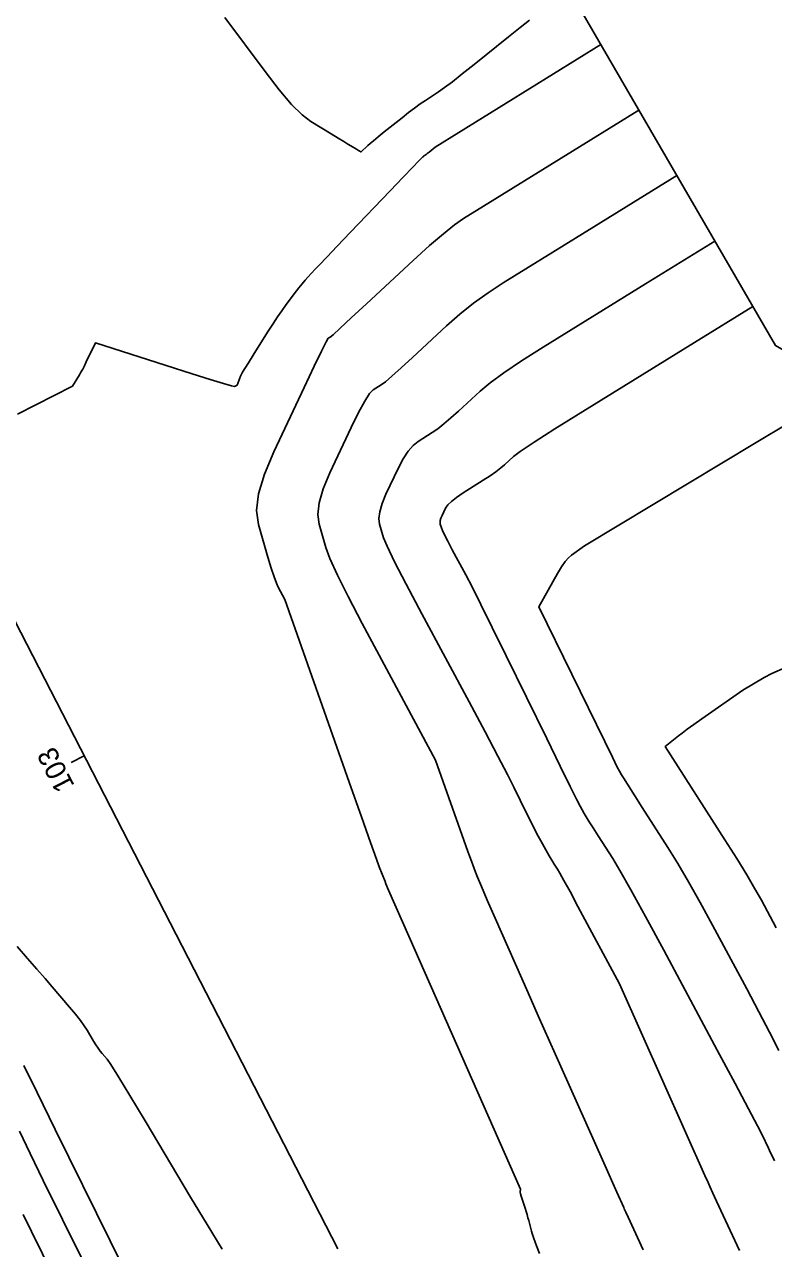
# Model space of a CAD drawing. Extents: x 1715724 to 1716561, y 394063 to 395906.
# Drawn here: x 1716227.9 to 1716279.5, y 394685.4 to 394769.7 of the extents above; entities that cross this region are included whole.
import ezdxf

# ---------------------------------------------------------------- set-up
doc = ezdxf.new("R2010")
doc.units = 0
for name, color, linetype in [('DT_X_Contour_Major', 7, 'Continuous'), ('DT_X_Contour_Minor', 7, 'Continuous'), ('DT_X_TIN_Hull', 7, 'Continuous'), ('GE_P_CL_10', 7, 'Continuous')]:
    doc.layers.add(name, color=color, linetype=linetype)

msp = doc.modelspace()

# ---------------------------------------------------------------- linework, layer by layer
at = {"layer": 'DT_X_Contour_Major'}
for points in [[(1716272.823, 394759.332), (1716265.845, 394755.011), (1716260.865, 394751.933), (1716259.819, 394751.253), (1716258.821, 394750.534), (1716257.87, 394749.777), (1716256.966, 394748.981), (1716254.621, 394746.807), (1716253.825, 394746.078), (1716253.199, 394745.52), (1716252.741, 394745.133), (1716252.452, 394744.917), (1716251.906, 394744.572), (1716251.658, 394744.312), (1716251.324, 394743.792), (1716250.902, 394743.011), (1716250.394, 394741.971), (1716248.923, 394738.849), (1716248.462, 394737.75), (1716248.183, 394736.794), (1716248.086, 394735.982), (1716248.17, 394735.314), (1716248.636, 394733.722), (1716248.925, 394732.948), (1716249.44, 394731.817), (1716250.183, 394730.331), (1716251.152, 394728.489), (1716256.206, 394719.064), (1716258.286, 394713.181), (1716258.43, 394712.779), (1716258.498, 394712.594), (1716258.61, 394712.303), (1716258.77, 394711.863), (1716258.95, 394711.359), (1716259.085, 394711.02), (1716259.357, 394710.38), (1716259.765, 394709.441), (1716260.309, 394708.201), (1716262.583, 394703.046), (1716263.279, 394701.476), (1716264.837, 394697.977), (1716267.799, 394691.34), (1716268.694, 394689.335), (1716269.164, 394688.27), (1716269.205, 394688.179), (1716269.305, 394687.953), (1716269.465, 394687.609), (1716269.869, 394686.746), (1716270.516, 394685.364)], [(1716235.034, 394683.408), (1716233.77, 394685.974), (1716229.993, 394693.646), (1716228.745, 394696.184), (1716227.834, 394698.044)]]:
    msp.add_lwpolyline(points, dxfattribs=at)
at = {"layer": 'DT_X_Contour_Minor'}
for points in [[(1716241.671, 394770.221), (1716244.453, 394766.49), (1716245.432, 394765.226), (1716246.282, 394764.231), (1716247.004, 394763.507), (1716247.598, 394763.052), (1716249.009, 394762.198), (1716249.49, 394761.907), (1716249.876, 394761.673), (1716250.166, 394761.496), (1716250.361, 394761.377), (1716250.753, 394761.136), (1716250.882, 394761.057), (1716250.974, 394761), (1716251.031, 394760.965), (1716251.051, 394760.952), (1716251.06, 394760.945), (1716251.54, 394761.396), (1716251.688, 394761.527), (1716251.925, 394761.726), (1716252.252, 394761.993), (1716252.668, 394762.328), (1716253.897, 394763.313), (1716254.343, 394763.664), (1716254.758, 394763.979), (1716255.144, 394764.258), (1716255.499, 394764.5), (1716256.407, 394765.098), (1716256.816, 394765.383), (1716257.361, 394765.791), (1716258.044, 394766.322), (1716258.863, 394766.976), (1716261.231, 394768.883), (1716262.038, 394769.528), (1716262.682, 394770.033)], [(1716227.391, 394742.901), (1716231.178, 394744.824), (1716231.663, 394745.6), (1716231.771, 394745.781), (1716231.886, 394745.991), (1716232.008, 394746.229), (1716232.138, 394746.496), (1716232.763, 394747.809), (1716239.425, 394745.677), (1716240.679, 394745.28), (1716241.586, 394745.002), (1716242.145, 394744.844), (1716242.358, 394744.805), (1716242.539, 394744.901), (1716242.661, 394745.253), (1716242.687, 394745.325), (1716242.713, 394745.393), (1716242.739, 394745.455), (1716242.765, 394745.512), (1716242.834, 394745.657), (1716242.903, 394745.779), (1716243.059, 394746.036), (1716243.302, 394746.427), (1716243.632, 394746.954), (1716244.626, 394748.538), (1716244.984, 394749.099), (1716245.311, 394749.594), (1716245.607, 394750.024), (1716245.872, 394750.389), (1716246.538, 394751.273), (1716246.779, 394751.588), (1716247.005, 394751.871), (1716247.216, 394752.12), (1716247.41, 394752.337), (1716247.907, 394752.872), (1716248.199, 394753.182), (1716248.701, 394753.71), (1716249.413, 394754.456), (1716250.335, 394755.42), (1716253.075, 394758.282), (1716253.977, 394759.225), (1716254.631, 394759.906), (1716255.036, 394760.327), (1716255.192, 394760.487), (1716255.276, 394760.566), (1716255.306, 394760.594), (1716255.334, 394760.619), (1716255.359, 394760.641), (1716255.381, 394760.659), (1716255.437, 394760.704), (1716255.458, 394760.72), (1716255.476, 394760.734), (1716255.494, 394760.747), (1716255.51, 394760.758), (1716255.552, 394760.785), (1716255.576, 394760.803), (1716255.62, 394760.837), (1716255.682, 394760.886), (1716255.762, 394760.95), (1716256.18, 394761.287), (1716267.588, 394768.353)], [(1716270.205, 394763.842), (1716259.514, 394757.222), (1716258.122, 394756.362), (1716257.515, 394755.94), (1716256.737, 394755.32), (1716255.788, 394754.501), (1716254.667, 394753.483), (1716251.452, 394750.503), (1716250.391, 394749.521), (1716249.618, 394748.811), (1716249.135, 394748.372), (1716248.94, 394748.204), (1716248.807, 394748.12), (1716248.665, 394747.884), (1716248.341, 394747.243), (1716247.834, 394746.194), (1716247.144, 394744.739), (1716245.06, 394740.315), (1716244.407, 394738.758), (1716244.011, 394737.405), (1716243.873, 394736.254), (1716243.993, 394735.307), (1716244.654, 394733.053), (1716244.883, 394732.29), (1716245.075, 394731.693), (1716245.23, 394731.261), (1716245.347, 394730.995), (1716245.806, 394730.138), (1716250.253, 394717.555), (1716251.097, 394715.169), (1716251.724, 394713.403), (1716252.133, 394712.257), (1716252.326, 394711.732), (1716252.722, 394710.714), (1716252.781, 394710.551), (1716252.966, 394710.125), (1716254.365, 394706.944), (1716262.044, 394689.522), (1716262.019, 394689.376), (1716262.024, 394689.319), (1716262.049, 394689.213), (1716262.095, 394689.055), (1716262.161, 394688.848), (1716262.365, 394688.227), (1716262.439, 394687.999), (1716262.507, 394687.779), (1716262.569, 394687.568), (1716262.625, 394687.366), (1716262.819, 394686.65), (1716262.867, 394686.481), (1716262.913, 394686.331), (1716262.955, 394686.201), (1716263.063, 394685.879), (1716263.16, 394685.622), (1716263.368, 394685.092)], [(1716275.44, 394754.821), (1716270.67, 394751.868), (1716263.608, 394747.505), (1716262.123, 394746.566), (1716260.904, 394745.749), (1716259.952, 394745.054), (1716259.265, 394744.48), (1716257.789, 394743.112), (1716257.26, 394742.634), (1716256.779, 394742.228), (1716256.347, 394741.894), (1716255.964, 394741.631), (1716255.006, 394741.024), (1716254.651, 394740.739), (1716254.306, 394740.341), (1716253.971, 394739.829), (1716253.644, 394739.203), (1716252.786, 394737.382), (1716252.517, 394736.741), (1716252.355, 394736.183), (1716252.298, 394735.71), (1716252.347, 394735.32), (1716252.619, 394734.392), (1716252.861, 394733.803), (1716253.381, 394732.734), (1716254.181, 394731.183), (1716255.259, 394729.152), (1716258.507, 394723.094), (1716259.614, 394721.022), (1716260.499, 394719.35), (1716261.161, 394718.079), (1716261.6, 394717.207), (1716262.477, 394715.415), (1716262.784, 394714.792), (1716263.05, 394714.267), (1716263.274, 394713.838), (1716263.455, 394713.508), (1716264.036, 394712.492), (1716264.169, 394712.265), (1716264.284, 394712.075), (1716264.38, 394711.921), (1716264.611, 394711.56), (1716264.764, 394711.298), (1716265.048, 394710.785), (1716265.464, 394710.019), (1716266.012, 394709.001), (1716268.874, 394703.664), (1716274.853, 394690.268), (1716274.906, 394690.147), (1716274.975, 394689.993), (1716275.03, 394689.868), (1716275.1, 394689.712), (1716275.305, 394689.252), (1716275.417, 394689.005), (1716275.856, 394688.061), (1716276.183, 394687.363), (1716277.149, 394685.304)], [(1716278.058, 394750.311), (1716274.052, 394747.834), (1716266.351, 394743.076), (1716264.427, 394741.879), (1716262.988, 394740.963), (1716262.034, 394740.33), (1716261.564, 394739.978), (1716260.958, 394739.416), (1716260.694, 394739.191), (1716260.36, 394738.937), (1716259.953, 394738.655), (1716259.475, 394738.344), (1716258.106, 394737.476), (1716257.645, 394737.166), (1716257.289, 394736.89), (1716257.039, 394736.646), (1716256.894, 394736.435), (1716256.649, 394735.915), (1716256.573, 394735.732), (1716256.526, 394735.573), (1716256.51, 394735.437), (1716256.524, 394735.326), (1716256.602, 394735.061), (1716256.671, 394734.893), (1716256.819, 394734.588), (1716257.048, 394734.145), (1716257.356, 394733.565), (1716258.283, 394731.835), (1716258.718, 394731), (1716259.328, 394729.793), (1716260.112, 394728.213), (1716261.07, 394726.26), (1716263.859, 394720.557), (1716264.788, 394718.662), (1716265.482, 394717.255), (1716265.94, 394716.336), (1716266.164, 394715.906), (1716266.448, 394715.409), (1716266.588, 394715.173), (1716266.795, 394714.837), (1716267.068, 394714.402), (1716267.409, 394713.867), (1716268.406, 394712.31), (1716268.906, 394711.476), (1716269.658, 394710.144), (1716270.663, 394708.312), (1716271.921, 394705.982), (1716275.61, 394699.103), (1716276.841, 394696.804), (1716277.767, 394695.064), (1716278.387, 394693.883), (1716278.702, 394693.262), (1716279.135, 394692.353), (1716279.29, 394692.029), (1716279.433, 394691.741), (1716279.562, 394691.489)], [(1716280.516, 394742.282), (1716278.284, 394740.942), (1716266.468, 394733.83), (1716265.556, 394733.194), (1716265.35, 394733.013), (1716265.124, 394732.742), (1716264.878, 394732.383), (1716264.611, 394731.934), (1716263.32, 394729.629), (1716267.856, 394720.355), (1716268.386, 394719.276), (1716268.725, 394718.593), (1716268.873, 394718.304), (1716269.012, 394718.061), (1716269.14, 394717.853), (1716269.42, 394717.409), (1716270.438, 394715.814), (1716272.2, 394713.06), (1716272.889, 394711.95), (1716273.633, 394710.688), (1716274.432, 394709.273), (1716275.287, 394707.704), (1716277.639, 394703.318), (1716278.472, 394701.751), (1716279.207, 394700.339), (1716279.842, 394699.081)], [(1716280.305, 394725.449), (1716279.365, 394725.035), (1716278.842, 394724.77), (1716277.376, 394723.888), (1716274.542, 394721.91), (1716273.987, 394721.52), (1716273.534, 394721.196), (1716273.185, 394720.938), (1716272.938, 394720.746), (1716272.028, 394720.008), (1716276.132, 394713.595), (1716276.95, 394712.304), (1716277.642, 394711.179), (1716278.21, 394710.22), (1716278.653, 394709.427), (1716279.668, 394707.533)], [(1716241.491, 394685.392), (1716240.453, 394687.102), (1716239.322, 394688.987), (1716236.182, 394694.243), (1716235.135, 394695.987), (1716234.35, 394697.274), (1716233.828, 394698.106), (1716233.568, 394698.482), (1716233.223, 394698.877), (1716233.089, 394699.041), (1716232.946, 394699.238), (1716232.795, 394699.467), (1716232.635, 394699.729), (1716232.197, 394700.469), (1716231.998, 394700.778), (1716231.728, 394701.147), (1716231.387, 394701.578), (1716230.976, 394702.069), (1716229.786, 394703.462), (1716229.3, 394704.027), (1716228.737, 394704.679), (1716228.095, 394705.417), (1716227.375, 394706.241)], [(1716231.82, 394684.758), (1716229.172, 394690.137), (1716228.266, 394691.99), (1716227.535, 394693.515)], [(1716229.87, 394683.542), (1716228.351, 394686.627), (1716227.788, 394687.795)]]:
    msp.add_lwpolyline(points, dxfattribs=at)
at = {"layer": 'DT_X_TIN_Hull'}
msp.add_lwpolyline([(1716374.782, 394668.715), (1716365.574, 394674.608), (1716357.292, 394676.294), (1716352.716, 394676.514), (1716327.751, 394677.716), (1716317.343, 394697.112), (1716309.021, 394713.588), (1716295.593, 394725.636), (1716283.618, 394745.304), (1716279.618, 394747.622), (1716265.79, 394771.45)], dxfattribs=at)
at = {"layer": 'GE_P_CL_10'}
for p, q in [((1716249.46, 394685.42), (1715852.538, 395456.564)), ((1716231.983, 394719.376), (1716231.094, 394718.919))]:
    msp.add_line(p, q, dxfattribs=at)

# ---------------------------------------------------------------- texts
msp.add_text('103', height=1.4, rotation=117.23573, dxfattribs=at).set_placement((1716231.355, 394717.318))

doc.saveas('drawing.dxf')
